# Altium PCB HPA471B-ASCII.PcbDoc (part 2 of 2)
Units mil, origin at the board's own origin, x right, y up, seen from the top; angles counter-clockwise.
Board outline 1305 x 1105 mil, 2 copper layers (Top Layer, Bottom Layer); 47 components, 32 nets, 115 pads, 21 vias.
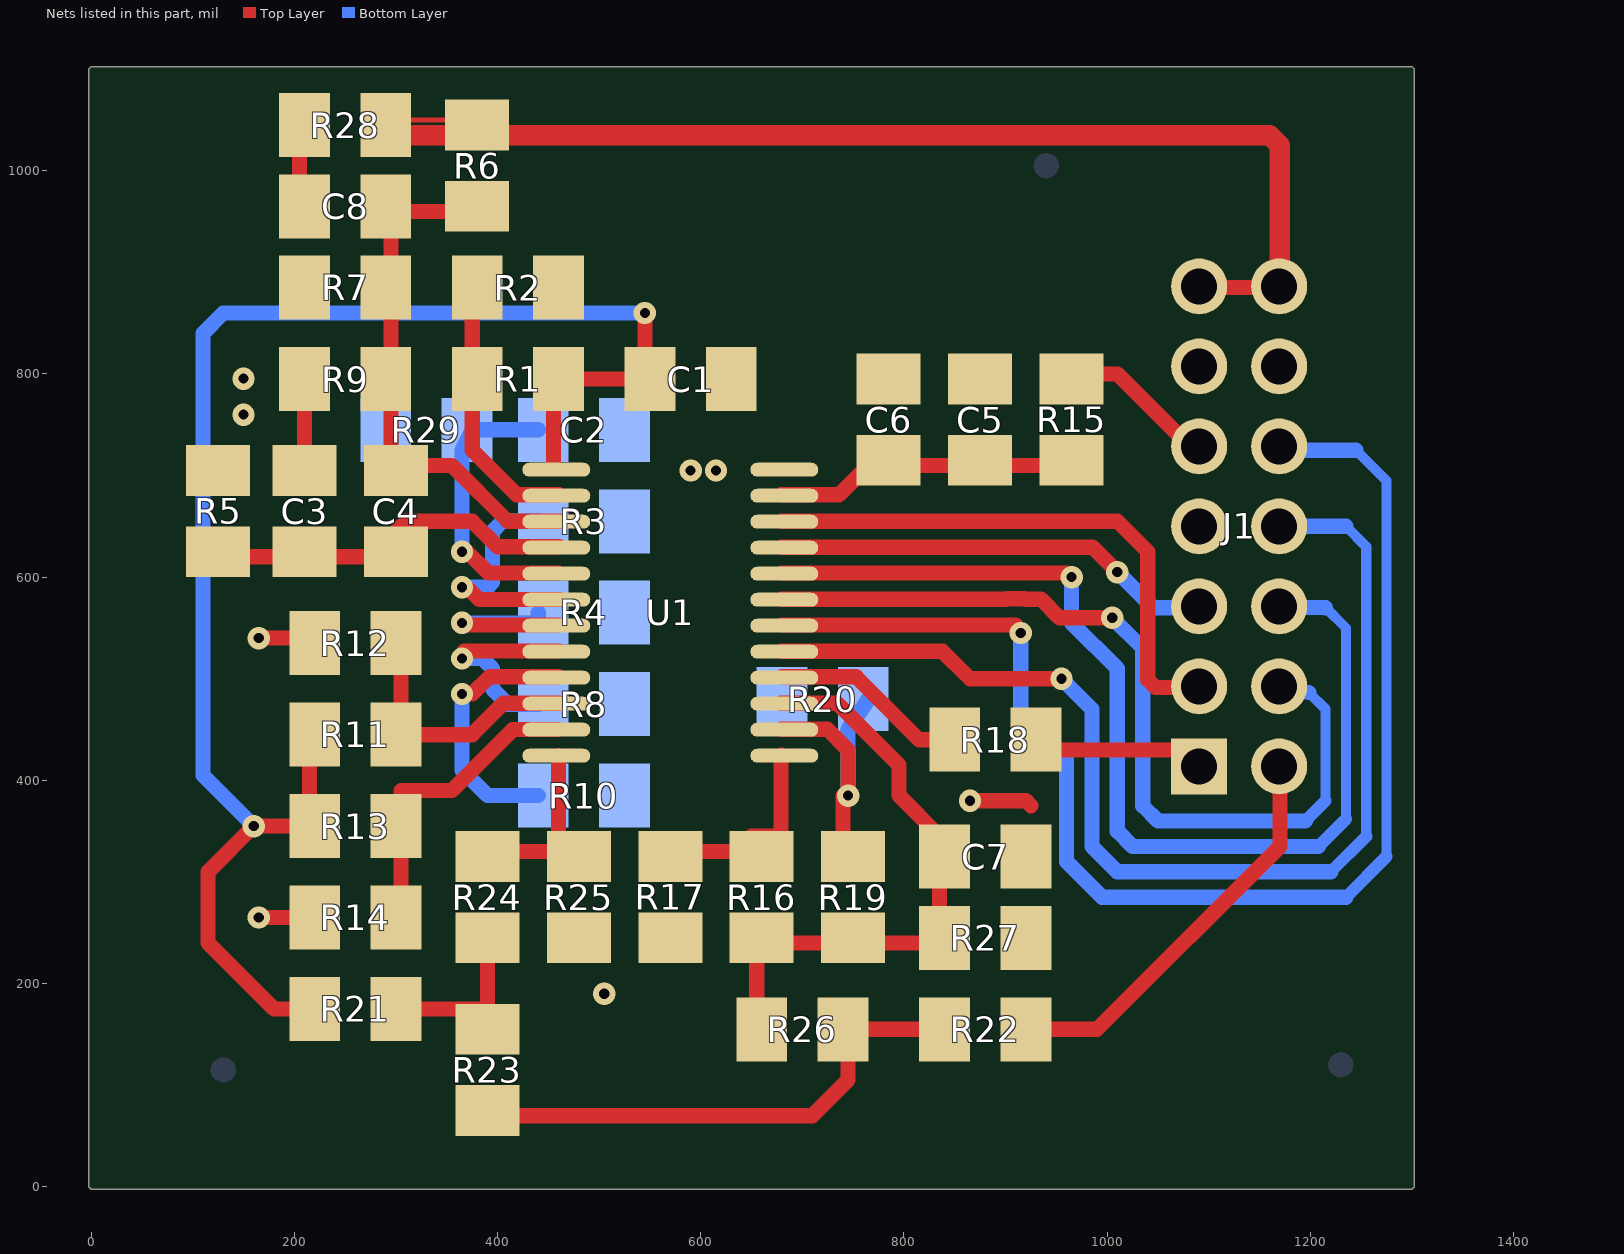
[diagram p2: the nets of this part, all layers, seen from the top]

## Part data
C1 C5: "CAP, CERM, 1 µF, 50 V, +/- 10%, X7R, 0805"
C2: "CAP, CERM, 0.15 µF, 50 V, +/- 10%, X7R, 0805"
C3: "CAP, CERM, 5600 pF, 50 V, +/- 10%, X7R, 0805"
C4: "CAP, CERM, 560 pF, 50 V, +/- 10%, X7R, 0805"
C6: "CAP, CERM, 0.1 µF, 25 V, +/- 10%, X7R, 0805"
C7 C8: "CAP, CERM, 330 pF, 50 V, +/- 10%, X7R, 0805"
FID1 FID2 FID3: "Fiducial mark.  There is nothing to buy or mount."
J1: "Header (shrouded), 2 mm, 7x2, R/A, TH"
Logo1: library part TI_Logo, "Texas Instrument Corporate Signature"
Logo2: library part Pb-Free
R1 R2 R7: "RES, 2.37k ohm, 1%, 0.125W, 0805"
R3 R4: "RES, 12.1k ohm, 1%, 0.125W, 0805"
R5 R12 R13 R16 R18 R19 R22 R23 R25 R27 R28: "RES, 1.00k ohm, 1%, 0.125W, 0805"
R6: "RES, 9.09k ohm, 1%, 0.125W, 0805"
R8: "RES, 56.2k ohm, 1%, 0.125W, 0805"
R9: "RES, 27.4k ohm, 1%, 0.125W, 0805"
R10: "RES, 13.3 k, 1%, 0.125 W, 0805"
R11: "RES, 61.9k ohm, 1%, 0.125W, 0805"
R14: "RES, 127k ohm, 1%, 0.125W, 0805"
R15: "RES, 22.6 ohm, 1%, 0.125W, 0805"
R17 R20 R21 R26: "RES, 0 ohm, 5%, 0.125W, 0805"
R24: "RES, 16.9k ohm, 1%, 0.125W, 0805"
R29: "RES, 825k ohm, 1%, 0.125W, 0805"
U1: "Green Phase-Shifted Full-Bridge Controller with Synchronous Rectification with Current Control, 97 % Duty Cycle, -40 to +125 degC, 24-pin TSSOP (PW), Green (RoHS & no Sb/Br)"
ZZ1 ZZ2 ZZ3: library part AssemblyNote

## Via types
v1: diameter 22, hole 10, Top Layer to Bottom Layer, 21 vias

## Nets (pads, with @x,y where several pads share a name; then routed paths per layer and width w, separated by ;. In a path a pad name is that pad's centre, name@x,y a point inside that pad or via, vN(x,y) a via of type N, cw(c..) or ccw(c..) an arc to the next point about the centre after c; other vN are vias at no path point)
ADEL: R19.1 R20.2 U1.14 | length 286.1
  Top Layer w15: U1.14@679.5,450.3 724.7,450.3 745,430 v1(745,385) 740,385 740,335 R19.1@750,330
  Bottom Layer w15: v1(745,385) 745,450 R20.2@765,480
ADELEF: R16.1 R17.2 U1.13 | length 216.9
  Top Layer w15: R17.2@570,330 660,330 650,345 679,345 679,424.2 U1.13@679.5,424.7
COMP: C3.1 C4.1 R5.1 U1.4 | length 381.1
  Top Layer w12: U1.4@460.5,629.6 U1.4@461,630
  Top Layer w15: R5.1@120,620 300,620 300,645 310,655 375,655 400,630 U1.4@461,630
CS: J1.2 R22.2 | length 402.1
  Top Layer w15: R22.2@925,155 990,155 1170,335 1170,415 J1.2@1168.7,412.8
CS0: C7.2 R16.2 R19.2 R26.1 R27.2 U1.15 | length 595.4
  Top Layer w12: U1.15@679,476 U1.15@679.5,475.9
  Top Layer w15: R26.1@655,155 655,235 660,240 665,240 750,240 795,240 835,240 835,245 835,325 835,345 795,385 795,415 734,476 U1.15@679,476
DCM: R24.1 R25.2 U1.12 | length 184.3
  Top Layer w15: R24.1@390,330 R25.2@460,330 ; U1.12@460,424.25 R25.2@460,330 ; R25.2@480,330 R25.2@460,330
DELAB: R3.2 U1.6 | length 234.7
  Top Layer w12: U1.6@460.5,578.4 U1.6@462,578
  Top Layer w15: v1(365,590) 370,590 382,578 U1.6@462,578
  Bottom Layer w15: v1(365,590) 390,590 395,595 395,645 405,655 R3.2@440,655
DELCD: R4.2 U1.7 | length 182.5
  Top Layer w12: U1.7@460,553 U1.7@460.5,552.8
  Top Layer w15: v1(365,555) 365,553 U1.7@460,553
  Bottom Layer w15: v1(365,555) 440,555 R4.2@440,565
DELEF: R8.2 U1.8 | length 206.2
  Top Layer w15: v1(365,520) 367.2,527.2 U1.8@460.5,527.2
  Bottom Layer w15: v1(365,520) 385,520 395,510 395,490 410,475 R8.2@440,475
EA+: R1.1 R2.2 U1.2 | length 263.9
  Top Layer w15: R2.2@375,885 375,725 419,681 460.5,681 U1.2@460.5,680.8
EA-: C4.2 C8.1 R6.1 R7.2 R9.2 U1.3 | length 531.4
  Top Layer w12: U1.3@460.5,655.2 U1.3@461,655
  Top Layer w15: R6.1@380,960 300,960 295,965 295,885 295,795 295,710 300,710 355,710 410,655 U1.3@461,655
GND: C1.1 C2.1 C5.1 C6.1 C7.1 J1.7 J1.11 J1.12 R2.1 R3.1 R4.1 R5.2 R7.1 R8.1 R10.1 R12.1 R14.1 R17.1 R20.1 R25.1 R27.1 R29.1 U1.24 | length 174.1
  Top Layer w15: v1(165,265) R14.1@220,265 ; v1(165,540) 215,540 R12.1@220,535 ; v1(865,380) 920,380 925,375
  other v1: 505,190 590,705 615,705 150,760 150,795.42
NetC3_2: C3.2 R9.1 | length 85.8
  Top Layer w15: R9.1@205,795 210,780 C3.2@210,710
NetC8_2: C8.2 R28.1 | length 80
  Top Layer w15: C8.2@205,965 R28.1@205,1045
NetR21_1: R21.1 R23.1 R24.2 | length 165
  Top Layer w15: R21.1@305,175 R23.1@390,175 ; R23.1@390,160 R23.1@390,175 ; R24.2@390,240 R23.1@390,175
NetR22_1: R22.1 R23.2 R26.2 | length 509.5
  Top Layer w15: R23.2@390,70 710,70 745,105 745,155 R22.1@835,155
OUTA: J1.3 U1.22 | length 552
  Top Layer w15: U1.22@679.5,655.1 1010,655 1040,625 1040,499 1047.5,491.5 J1.3@1090,491.5
OUTB: J1.5 U1.21 | length 436.1
  Top Layer w12: U1.21@679.5,629.5 U1.21@680,630
  Top Layer w15: U1.21@679.5,629.5 985.5,629.5 v1(1010,605)
  Bottom Layer w15: v1(1010,605) 1045,570 1090,570 J1.5@1090,570.2
OUTC: J1.6 U1.20 | length 1060.5
  Top Layer w12: U1.20@679.5,603.9 U1.20@680,604
  Top Layer w15: U1.20@680,604 960,604 v1(965,600)
  Bottom Layer w10: 1215,570 1235,550 1235,361.98
  Bottom Layer w12: 1208.02,335 1235,361.98
  Bottom Layer w15: v1(965,600) 965,555 1010,510 1010,350 1025,335 1208.02,335 ; J1.6@1168.7,570.2 1215,570
OUTD: J1.4 U1.19 | length 869
  Top Layer w15: U1.19@679.5,578.3 900.66,578.3 901.19,578.84 918.81,578.84 919.34,578.3 934.7,578.3 953,560 v1(1005,560)
  Bottom Layer w10: 1198.5,486.5 1215,470 1215,380
  Bottom Layer w12: 1195,360 1215,380
  Bottom Layer w15: v1(1005,560) 1035,530 1035,375 1050,360 1195,360 ; J1.4@1168.7,491.5 1198.5,486.5
OUTE: J1.10 U1.18 | length 1321.9
  Top Layer w12: U1.18@679.5,552.7 U1.18@680,553
  Top Layer w15: U1.18@680,553 910,553 v1(915,545)
  Bottom Layer w10: 1245,725 1275,695 1275,325
  Bottom Layer w12: 1235,285 1275,325
  Bottom Layer w15: v1(915,545) 915,465 960,420 960,320 995,285 1235,285 ; J1.10@1168.7,727.6 1170,730 1175,725 1245,725
OUTF: J1.8 U1.17 | length 1139.1
  Top Layer w12: U1.17@679.5,527.1 U1.17@680,527
  Top Layer w15: U1.17@680,527 838,527 865,500 v1(955,500)
  Bottom Layer w10: 1235,650 1255,630 1255,344.83
  Bottom Layer w12: 1220.17,310 1255,344.83
  Bottom Layer w15: v1(955,500) 985,470 985,335 1010,310 1220.17,310 ; J1.8@1168.7,648.9 1170,650 1235,650
RSUM: R13.1 R14.2 U1.11 | length 305.5
  Top Layer w12: U1.11@460,450 U1.11@460.5,450.4
  Top Layer w15: R14.2@305,265 305,355 305,390 355,390 415,450 U1.11@460,450
RT: R11.2 R12.2 U1.10 | length 258.8
  Top Layer w12: U1.10@460.5,476 U1.10@461,476
  Top Layer w15: R12.2@305,535 305,445 375,445 406,476 U1.10@460.5,476
SS/EN: C2.2 R29.2 U1.5 | length 291.6
  Top Layer w12: U1.5@460,604 U1.5@460.5,604
  Top Layer w15: v1(365,625) 370,625 391,604 U1.5@460,604
  Bottom Layer w15: v1(365,625) 365,725 375,745 C2.2@440,745
SYNC: J1.1 R18.2 | length 173.4
  Top Layer w15: R18.2@935,440 945,430 1085,430 1090,425 J1.1@1090,412.8
SYNC0: R18.1 U1.16 | length 191.4
  Top Layer w12: U1.16@679.5,501.5 U1.16@680,502
  Top Layer w15: U1.16@680,502 753,502 815,440 R18.1@845,440
TMIN: R10.2 U1.9 | length 263
  Top Layer w12: U1.9@460,502 U1.9@460.5,501.6
  Top Layer w15: v1(365,485) 375,485 392,502 U1.9@460,502
  Bottom Layer w15: v1(365,485) 365,410 390,385 R10.2@440,385
VBIAS: J1.9 R15.2 | length 156.4
  Top Layer w15: R15.2@965,800 1010,800 1080,730 1090,730 J1.9@1090,727.6
VDD: C5.2 C6.2 R15.1 U1.23 | length 298.6
  Top Layer w12: U1.23@679,681 U1.23@679.5,680.7
  Top Layer w15: U1.23@679,681 736,681 765,710 785,710 875,710 R15.1@965,710
VOUT: J1.13 J1.14 R6.2 R28.2 | length 1227.4
  Top Layer w5: R28.2@285,1035 300,1050 R6.2@380,1050
  Top Layer w15: J1.13@1090,885 1168.7,885 J1.14@1170,885 ; J1.14@1175,890 J1.14@1180,895
  Top Layer w20: R28.2@285,1035 1160,1035 1170,1025 1170,885 1175,885 J1.14@1175,890
VREF: C1.2 R1.2 R11.1 R13.2 R21.2 U1.1 | length 1602.4
  Top Layer w12: U1.1@455,707 455.6,706.4 U1.1@460.5,706.4
  Top Layer w15: R21.2@215,175 180,175 115,240 115,310 v1(160,355) 215,355 R11.1@215,445 ; U1.1@455,707 455,785 R1.2@465,795 ; R1.2@460,795 R1.2@465,795 ; v1(545,860) 545,795 R1.2@465,795
  Bottom Layer w15: v1(160,355) 110,405 110,840 130,860 v1(545,860)
pads on no net: FID1.1 FID2.1 FID3.1

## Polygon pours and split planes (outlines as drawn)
GND on Top Layer "Top Layer, Top-GND" (solid, pour order 2): 1055,690 1050,685 1050,637.07 1051.47,633.54 1073.54,611.46 1077.07,610 1115,610 1120,615 1120,685 1115,690
GND on Top Layer "Top Layer, Top-GND 1" (solid, pour order 4): 1060,830 1055,825 1055,790 1060,785 1200,785 1205,790 1205,825 1200,830
GND on Top Layer "Top Layer, Top-GND 2" (solid, remove dead copper, pour order 6): 25,50 32.32,32.32 50,25 1250,25 1267.68,32.32 1275,50 1275,1050 1267.68,1067.68 1250,1075 50,1075 32.32,1067.68 25,1050
GND on Bottom Layer "Bottom Layer, Bottom-GND" (solid, pour order 8): 1055,690 1050,685 1050,637.07 1051.47,633.54 1073.54,611.46 1077.07,610 1115,610 1120,615 1120,685 1115,690
GND on Bottom Layer "Bottom Layer, Bottom-GND 1" (solid, pour order 10): 1050,830 1045,825 1045,790 1050,785 1215,785 1220,790 1220,825 1215,830
GND on Bottom Layer "Bottom Layer, Bottom-GND 2" (solid, remove dead copper, pour order 12): 30,50 37.32,32.32 55,25 1255,25 1272.68,32.32 1280,50 1280,1050 1272.68,1067.68 1255,1075 55,1075 37.32,1067.68 30,1050

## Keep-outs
Keep-Out Layer, Board:
  lines w5: 0,0 0,1100 1300,1100 1300,0 0,0

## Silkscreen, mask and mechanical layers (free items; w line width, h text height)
Top Overlay, Top Silk:
  lines w5: 120,755 160,755 167.5,747.5 ; 390,370 390,395 ; 495,820 510,835 510,845 ; 600,187.5 610,200 ; 765,370 765,415
  text "HPA471B" at 875,25 h37.5
Bottom Overlay, Bot Silk:
  text ".PCB_Rev" at 330,275 h37.5
  text "REV" at 460,275 h37.5
  text ".PRJ_Number" at 1095,270 h37.5
M1 Board Outline:
  lines w5: 0,0 1300,0 1300,1100 0,1100 0,0
M5 Assembly Top:
  lines w10: -935,-1501.67 5665,-1501.67 ; -935,-1298.33 5667,-1298.33 ; -935,-1095 -935,-1705 3070,-1705 5667,-1705 5667,-1095 -934.5,-1095 -934.5,-1705 641,-1705 ; 1530,-1705 1530,-1095 ; 2797,-1298.33 2797,-1095 ; 3637,-1298.33 3637,-1095 ; 4259,-1711.5 4259,-1508.67
  text "COMPONENTS MARKED 'DNP' SHOULD NOT BE POPULATED." at 3725.5,2730 h60
  text "ASSEMBLY VARIANT:" at 3725,2614.5 h60
  text ".VariantName" at 4761,2614.5 h60
  text "PCB VIEWED FROM TOP SIDE" at -871.5,-1227.17 h60
  text "BOARD #:" at 1605,-1227.17 h60
  text ".PRJ_Number" at 2150.5,-1227.17 h60
  text "REV:" at 2995,-1227.17 h60
  text ".PCB_Rev" at 3286.5,-1227.17 h60
  text "SVN REV:" at 3833,-1227.17 h60
  text ".VersionControl_RevNumber" at 4339,-1227.17 h60
  text "IGNORE ->" at -871.5,-1429.99 h60
  text "PLOT NAME =" at -871.5,-1635.84 h60
  text ".plot_File_Name" at -66,-1635.84 h60
  text "GENERATED    :" at 1607,-1635.84 h60
  text ".Print_Date" at 2476.5,-1635.84 h60
  text ".Print_Time" at 3205.5,-1635.84 h60
  text "TEXAS INSTRUMENTS" at 4470,-1635.84 h60
M6 Assembly Bottom:
  lines w5: 20,95 20,20 95,20
M7 LPKF Text Top:
  lines w5: -100,0 25,0 ; 0,-100 0,25
M9 Title Sheet:
  lines w10: -1136.5,466.5 -936.5,466.5 ; -1136.5,2841.5 -936.5,2841.5 ; -1136.5,5216.5 -936.5,5216.5 ; 1363.5,-1908.5 1363.5,-1708.5 ; 1363.5,7391.5 1363.5,7591.5 ; 3863.5,-1908.5 3863.5,-1708.5 ; 3863.5,7391.5 3863.5,7591.5 ; 5676,-1708.5 5676,-1098.5 10658.5,-1098.5 ; 6363.5,-1908.5 6363.5,-1708.5 ; 6363.5,7391.5 6363.5,7591.5 ; 8863.5,-1908.5 8863.5,-1708.5 ; 8863.5,7391.5 8863.5,7591.5 ; 10658.5,-1708.5 10658.5,-1098.5 ; 10658.5,-1398.5 13658.5,-1398.5 ; 10658.5,-798.5 13658.5,-798.5 ; 10659.5,-204.5 13659.5,-204.5 ; 11363.5,-1908.5 11363.5,-1708.5 ; 11363.5,7391.5 11363.5,7591.5 ; 12163.5,-1698.5 12163.5,-1098.5 ; 13658.5,-1098.5 10658.5,-1098.5 ; 13658.5,-498.5 10658.5,-498.5 ; 13663.5,-508.5 13663.5,-1708.5 ; 13663.5,296 10659.5,296 10658.5,296 10658.5,-204.5 10658.5,-498.5 ; 13663.5,466.5 13863.5,466.5 ; 13663.5,2841.5 13863.5,2841.5 ; 13663.5,5216.5 13863.5,5216.5 ; 10658.5,-1098.5 10658.5,-498.5 ; 13663.5,-1708.5 13663.5,7391.5 -936.5,7391.5 -936.5,-1708.5 13663.5,-1708.5 ; -1136.5,-1908.5 -1136.5,7591.5 13863.5,7591.5 13863.5,-1908.5 -1136.5,-1908.5
  text "1" at 94.84,7461.5 h70
  text "2" at 2590.5,7461.5 h70
  text "3" at 5079.84,7461.5 h70
  text "4" at 7586.51,7461.5 h70
  text "5" at 10085.5,7461.5 h70
  text "6" at 12590.5,7461.5 h70
  text "A" at -1061.5,6318.5 h70
  text "A" at 13738.5,6318.5 h70
  text "B" at -1061.5,3938.5 h70
  text "B" at 13738.5,3938.5 h70
  text "C" at -1061.5,1563.5 h70
  text "C" at 13738.5,1563.5 h70
  text "PROJECT TITLE:" at 10698.5,-297.5 h45
  text ".PRJ_Title" at 10748.5,-430.83 h70
  text "DESIGNED FOR:" at 10698.5,-598.5 h45
  text ".PRJ_Customer" at 10748.5,-738.5 h70
  text "D" at -1061.5,-806.5 h70
  text "D" at 13738.5,-806.5 h70
  text "FILE NAME:" at 10698.5,-898.5 h45
  text ".PCB_File_Name_No_Path" at 10748.5,-1018.5 h70
  text "Texas Instruments (TI) and/or its licensors do not warrant the accuracy or completeness of this specification" at 5729,-1180.34 h45
  text "ENGINEER:" at 10698.5,-1188.5 h45
  text "LAYOUT BY:" at 12203.5,-1188.5 h45
  text "or any information contained therein. TI and/or its licensors do not warrant that this design will meet" at 5684.01,-1293 h45
  text ".PRJ_Engineer" at 10748.5,-1343.49 h70
  text ".PCB_Layout" at 12254,-1343.49 h70
  text "the specifications, will be suitable for your application or fit for any particular purpose, or will operate in" at 5684.01,-1405.67 h45
  text ".Layer_Name" at -68,-1433.49 h60
  text "ALTIUM DESIGNER VERSION:" at 12203.5,-1498.5 h45
  text "an implementation. TI and/or its licensors do not warrant that the design is production worthy. You should" at 5684.01,-1518.33 h45
  text "completely validate and test your design implementation to confirm the system functionality for your application." at 5729,-1631 h45
  text ".print_Scale" at 10748.5,-1631.83 h70
  text ".Application_BuildNumber" at 12254,-1631.83 h70
  text "1" at 94.84,-1838.5 h70
  text "2" at 2590.5,-1838.5 h70
  text "3" at 5079.84,-1838.5 h70
  text "4" at 7586.51,-1838.5 h70
  text "5" at 10085.5,-1838.5 h70
  text "6" at 12590.5,-1838.5 h70
M10 Fab Notes:
  drawing of 207 lines, arcs and shapes, not listed
  text "DESIGN INFORMATION" at 11738.52,6238.15 h60
  text "(REFER ALSO ARRAY/PANEL PROFILING INFORMATION)" at 11376.96,6076.43 h60
  text "BOARD SIZE" at 10690.96,6072.15 h60
  text "33.02mm" at 11153.28,5944.33 h60
  text "X" at 11658.96,5944.33 h60
  text "27.94mm" at 11890.28,5944.33 h60
  text "Number of Layers :" at 11093.96,5747.15 h60
  text "2" at 12188.77,5737.15 h60
  text "MIN. TRACK WIDTH:" at 11093.96,5608.15 h60
  text "10" at 12190.2,5608.15 h60
  text "MIL" at 12344.96,5608.15 h60
  text "MIN. CLEARANCE:" at 11093.96,5476.15 h60
  text "8" at 12190.2,5476.15 h60
  text "MIL" at 12344.96,5476.15 h60
  text "MIN. VIA PAD SIZE:" at 11093.96,5344.15 h60
  text "24" at 12160.21,5344.15 h60
  text "MIL" at 12344.96,5344.15 h60
  text "0.05mm (2MIL)" at 11788.96,5202.44 h60
  text "MINIMUM ANNULAR RING" at 10764.73,5198.15 h60
  text "EXTERNAL" at 12496.96,5198.15 h60
  text "PER" at 10964.73,5080.15 h60
  text "IPC-D-275 CLASS 2 LEVEL C" at 11184.73,5080.15 h60
  text "MIL, HOLES" at 12672.96,4967.86 h60
  text "+/-" at 12280.5,4967.15 h60
  text "+/-" at 13134.5,4967.15 h60
  text "REGISTRATION TOLERANCES:" at 10764.73,4962.15 h60
  text "METAL" at 11964.5,4962.15 h60
  text "5" at 12540.7,4962.15 h60
  text "5" at 13373.7,4962.15 h60
  text "MIL" at 13489.96,4962.15 h60
  text "MATERIAL:" at 10689.96,4752.69 h60
  text "FR-4 High Tg" at 11676.4,4612.36 h60
  text "X" at 11520.1,4606.02 h60
  text "FR-4" at 11150.96,4603.79 h60
  text "OTHER" at 12598.96,4603.79 h60
  text "62 MIL (1.6mm) +/-10%" at 11431.06,4441.07 h60
  text "THICKNESS:" at 10764.73,4436.79 h60
  text "X" at 11302.9,4436.79 h60
  text "OTHER" at 12715.96,4436.79 h60
  text "TOLERANCE:" at 10764.73,4278.79 h60
  text "X" at 11604.03,4278.79 h60
  text "ANSI IPC-6012 TYPE 3 CLASS 2" at 11790.98,4278.79 h60
  text "OTHER +/-" at 11790.96,4122.79 h60
  text "BOW & TWIST:" at 10764.73,3965.79 h60
  text "X" at 11604.03,3965.79 h60
  text "ANSI IPC-6012 TYPE 3 CLASS 2" at 11790.98,3965.79 h60
  text "OTHER +/-" at 11790.96,3807.28 h60
  text "COPPER THICKNESS (FINISHED):" at 10689.96,3671.79 h60
  text "X" at 12215,3525 h60
  text "2.8MIL (2oz)" at 12336.96,3524.29 h60
  text "1.4MIL (1oz)" at 11569.96,3519.07 h60
  text "4oz" at 13063.96,3519.07 h60
  text "OUTER:" at 11046.96,3514.79 h60
  text "1.4MIL (1oz)" at 11569.96,3362.07 h60
  text "2.8MIL (2oz)" at 12336.96,3362.07 h60
  text "N/A" at 13063.5,3362.43 h60
  text "X" at 12930,3360 h60
  text "INNER SIGNAL:" at 10757.88,3357.79 h60
  text "DRILLING:" at 10689.96,3218.79 h60
  text "REFERENCE:" at 10764.73,3101.79 h60
  text "X" at 11412.96,3101.79 h60
  text "AS SHOWN" at 11599.96,3101.79 h60
  text "X" at 12313.96,3101.79 h60
  text "NC_DRILL FILES" at 12450.96,3101.79 h60
  text "X" at 12642.22,2955.47 h60
  text "PTH MIN COPPER THICKNESS:" at 10764.73,2943.79 h60
  text "1MIL" at 12251.96,2943.79 h60
  text "1oz" at 12748.96,2943.79 h60
  text "BOARD FINISH:" at 10689.96,2784.79 h60
  text "SILKSCREEN:" at 10845.18,2666.79 h60
  text "X" at 11793.96,2666.79 h60
  text "TOP" at 11919.96,2666.79 h60
  text "X" at 12303.96,2666.79 h60
  text "BOTTOM" at 12430.96,2666.79 h60
  text "SILKSCREEN COLOR:" at 10845.18,2499.79 h60
  text "X" at 11792.92,2499.79 h60
  text "WHITE" at 11919.96,2499.79 h60
  text "OTHER" at 12430.96,2499.79 h60
  text "SOLDER RESIST COLOR:" at 10845.18,2329.79 h60
  text "X" at 11412.92,2170.59 h60
  text "GREEN" at 11539.96,2170.59 h60
  text "BLUE" at 12130.96,2170.59 h60
  text "OTHER" at 12668.96,2170.59 h60
  text "IMMERSION GOLD (ENIG)" at 11750.96,1982.07 h60
  text "X" at 11570,1980 h60
  text "SURFACE FINISH:" at 10689.96,1977.79 h60
  text "IMM. TIN/SILVER OR EQUIV" at 11019.5,1820.79 h60
  text "OTHER" at 12450.96,1820.79 h60
  text "ARRAY/PANEL:" at 10689.96,1641.79 h60
  text "CUT AND TRIM PER MECH LAYER 1" at 11750.96,1637.5 h60
  text "N.C. ROUTE" at 11750.96,1485.79 h60
  text "V. SCORE" at 12616.96,1485.79 h60
  text "X" at 12420.52,1474.79 h60
  text "CERTIFICATION:" at 10689.96,1348.79 h60
  text "MATERIALS AND WORKMANSHIP FOR ALL PCBS" at 11414.96,1348.79 h60
  text "TO MEET OR EXCEED THE REQUIREMENTS OF:" at 11414.96,1250.79 h60
  text "X" at 11041.46,1114.28 h60
  text "ANSI IPC-A-600F CLASS ->" at 11180.46,1114.28 h60
  text "X" at 12819.52,1114.28 h60
  text "2" at 12938.46,1114.28 h60
  text "1" at 12623.46,1112.79 h60
  text "3" at 13292.46,1112.79 h60
  text "X" at 11043.52,954.79 h60
  text "UL 94V-0" at 11180.46,954.79 h60
  text "X" at 11855.52,954.79 h60
  text "RoHS" at 11992.46,954.79 h60
  text "OTHER" at 12636.86,954.79 h60
  text "PER ORDER" at 13033.92,954.79 h60
  text "ADDITIONAL REQUIREMENTS:" at 10689.96,813.79 h60
  text "MICROSECTION:" at 10764.73,698.79 h60
  text "YES" at 11670.46,698.79 h60
  text "REQUIRED" at 12531.96,542.64 h60
  text "BARE BOARD ELEC. TEST:" at 10764.73,539.79 h60
  text "NONE" at 12070.46,539.79 h60
  text "PER ORDER" at 13123.96,539.79 h60
  text "X" at 12395,535 h60
  text "X" at 13092.22,385.47 h60
  text "MANUFACTURER'S ID/LOGO:" at 10764.73,382.79 h60
  text "RAIL" at 12230.46,378.5 h60
  text "METAL" at 12722.27,378.5 h60
  text "SILK" at 13233.96,378.5 h60
  text ".Layer_Name" at -65.5,-1430.34 h60
M11 Gerber Information:
  lines w10: -937,-1500.17 5663,-1500.17 ; -937,-1296.83 5665,-1296.83 ; -937,-1093.5 -937,-1703.5 3068,-1703.5 5665,-1703.5 5665,-1093.5 -936.5,-1093.5 -936.5,-1703.5 639,-1703.5 ; 1528,-1703.5 1528,-1093.5 ; 2795,-1296.83 2795,-1093.5 ; 3635,-1296.83 3635,-1093.5 ; 4257,-1710 4257,-1507.17
  text "ALL ARTWORK VIEWED FROM TOP SIDE" at -873.5,-1225.67 h60
  text "BOARD #:" at 1603,-1225.67 h60
  text ".PRJ_Number" at 2148.5,-1225.67 h60
  text "REV:" at 2993,-1225.67 h60
  text ".PCB_Rev" at 3284.5,-1225.67 h60
  text "SVN REV:" at 3831,-1225.67 h60
  text ".VersionControl_RevNumber" at 4337,-1225.67 h60
  text "LAYER NAME =" at -873.5,-1428.49 h60
  text "PLOT NAME =" at -873.5,-1634.34 h60
  text ".plot_File_Name" at -68,-1634.34 h60
  text "GENERATED    :" at 1605,-1634.34 h60
  text ".Print_Date" at 2474.5,-1634.34 h60
  text ".Print_Time" at 3203.5,-1634.34 h60
  text "TEXAS INSTRUMENTS" at 4468,-1634.34 h60
M12 Stackup:
  lines w8: 10770,6972.33 13505,6972.33 ; 10770,7127.93 13505,7127.93 ; 10710,6415 ccw(c10760,6415) 10760,6365 13515,6365 ccw(c13515,6415) 13565,6415 13565,7315 ccw(c13515,7315) 13515,7365 10760,7365 ccw(c10760,7315) 10710,7315 10710,6415
  text "Layer Stack Up Detail for: HPA471B.PcbDoc" at 10770,7198.47 h65
  text "Layer" at 10770,7069.93 h36
  text "Gerber" at 11814.03,7069.93 h36
  text "Copper" at 12278.64,7069.93 h36
  text "Dielectric" at 12802.03,7069.93 h36
  text "Name" at 10770,6997.93 h36
  text "Document" at 11814.03,6997.93 h36
  text "Thickness" at 12278.64,6997.93 h36
  text "Material" at 12802.03,6997.93 h36
  text "Top Solder Mask" at 10770,6856.77 h50
  text "(.GTS)" at 11814.03,6856.77 h50
  text "Solder Resist" at 12802.03,6856.77 h50
  text "Top Layer, Top" at 10770,6708.02 h50
  text "(.GTL)" at 11814.03,6708.02 h50
  text "2.8mil" at 12278.64,6708.02 h50
  text "FR-4" at 12802.03,6633.65 h50
  text "Bottom Layer, Bottom" at 10770,6559.27 h50
  text "(.GBL)" at 11814.03,6559.27 h50
  text "2.8mil" at 12278.64,6559.27 h50
  text "Bottom Solder Mask" at 10770,6410.52 h50
  text "(.GBS)" at 11814.03,6410.52 h50
  text "Solder Resist" at 12802.03,6410.52 h50
  text ".Layer_Name" at -68,-1428.49 h60
Drill Drawing:
  text ".legend" at 3564.55,1200.62 h60
  text "Drill Table" at 3589.55,1015.62 h60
